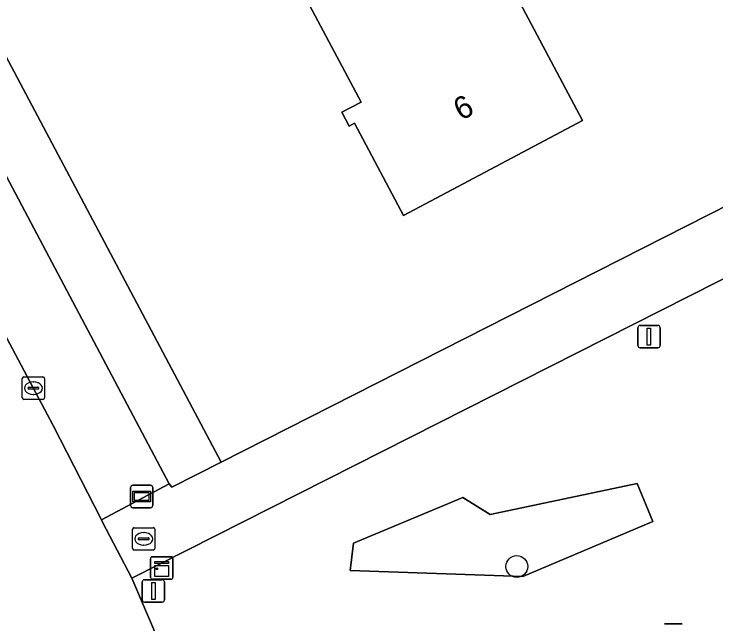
# Model space of a CAD drawing. Extents: x 162417 to 163722, y 384268 to 385417.
# Drawn here: x 163569.95 to 163601.33, y 384787.57 to 384814.82 of the extents above; entities that cross this region are included whole.
import ezdxf

# ---------------------------------------------------------------- set-up
doc = ezdxf.new("R2010")
doc.units = 0
for name, color, linetype in [('IMGEO_Berm_groen', 7, 'Continuous'), ('IMGEO_Boom', 7, 'Continuous'), ('IMGEO_Brandkraan', 7, 'Continuous'), ('IMGEO_Erf', 7, 'Continuous'), ('IMGEO_Groenvoorziening', 7, 'Continuous'), ('IMGEO_Kast', 7, 'Continuous'), ('IMGEO_Kolk', 7, 'Continuous'), ('IMGEO_Lichtmast', 7, 'Continuous'), ('IMGEO_Pand', 7, 'Continuous'), ('IMGEO_Pand_nummerreeks', 7, 'Continuous'), ('IMGEO_Rijbaan_lokaal_gesloten', 7, 'Continuous'), ('IMGEO_Verklikker', 7, 'Continuous'), ('IMGEO_Voetpad_open', 7, 'Continuous')]:
    doc.layers.add(name, color=color, linetype=linetype)

msp = doc.modelspace()

# ---------------------------------------------------------------- linework, layer by layer
at = {"layer": 'IMGEO_Berm_groen'}
msp.add_lwpolyline([(163567.994, 384810.595), (163566.174, 384809.627), (163566.069, 384809.515), (163565.334, 384808.395), (163571.704, 384796.445), (163573.858, 384792.219), (163576.893, 384793.832)], close=True, dxfattribs=at)
at = {"layer": 'IMGEO_Boom'}
msp.add_circle((163592.424, 384790.139), 0.489, dxfattribs=at)
at = {"layer": 'IMGEO_Brandkraan'}
for p, q in [((163575.25, 384790.949), (163575.25, 384791.801)), ((163575.325, 384791.875), (163576.177, 384791.875)), ((163575.738, 384791.655), (163575.763, 384791.655)), ((163576.251, 384791.801), (163576.251, 384790.949)), ((163575.509, 384791.369), (163575.509, 384791.381)), ((163575.947, 384791.332), (163575.549, 384791.332)), ((163575.552, 384791.418), (163575.95, 384791.418)), ((163575.993, 384791.381), (163575.993, 384791.369)), ((163575.761, 384791.095), (163575.736, 384791.095)), ((163576.177, 384790.875), (163575.325, 384790.875))]:
    msp.add_line(p, q, dxfattribs=at)
for points in [[(163575.25, 384790.949), (163575.25, 384791.801)], [(163575.325, 384791.875), (163576.177, 384791.875)], [(163576.251, 384791.801), (163576.251, 384790.949)], [(163576.177, 384790.875), (163575.325, 384790.875)]]:
    msp.add_lwpolyline(points, dxfattribs=at)
for centre, radius, start, end in [((163575.327, 384791.799), 0.0765, 91.552, 178.448), ((163575.327, 384791.799), 0.0765, 91.552, 178.448), ((163576.175, 384791.799), 0.0765, 1.552, 88.448), ((163576.175, 384791.799), 0.0765, 1.552, 88.448), ((163575.549, 384791.378), 0.0403, 85.8775, 175.7526), ((163575.546, 384791.368), 0.0366, 178.938, 274.7102), ((163575.95, 384791.375), 0.043, 264.8664, 352.4533), ((163575.954, 384791.38), 0.0386, 1.7309, 96.639), ((163575.327, 384790.951), 0.0765, 181.552, 268.448), ((163575.327, 384790.951), 0.0765, 181.552, 268.448), ((163576.175, 384790.951), 0.0765, 271.552, 358.448), ((163576.175, 384790.951), 0.0765, 271.552, 358.448)]:
    msp.add_arc(centre, radius, start, end, dxfattribs=at)
for centre, major_axis, ratio, start_param, end_param in [((163575.737, 384791.375), (-0.387, 0.002), 0.722429, 4.712389, 7.853982), ((163575.762, 384791.375), (-0.39, 0.002), 0.717154, 1.570796, 4.712389)]:
    msp.add_ellipse(centre, major_axis=major_axis, ratio=ratio, start_param=start_param, end_param=end_param, dxfattribs=at)
at = {"layer": 'IMGEO_Erf'}
for points in [[(163552.107, 384845.87), (163579.211, 384794.807), (163618.849, 384814.904)], [(163591.933, 384816.532), (163595.361, 384810.069), (163587.359, 384805.824), (163585.173, 384809.945), (163584.931, 384809.816), (163584.605, 384810.432), (163585.463, 384810.887), (163582.447, 384816.574)]]:
    msp.add_lwpolyline(points, dxfattribs=at)
at = {"layer": 'IMGEO_Groenvoorziening'}
msp.add_lwpolyline([(163585.393, 384778.896), (163588.913, 384780.464), (163589.864, 384780.875), (163628.147, 384799.526), (163621.295, 384812.929), (163575.222, 384789.612), (163577.885, 384783.374), (163577.57, 384783.198), (163577.982, 384782.302)], dxfattribs=at)
for points in [[(163592.689, 384789.696), (163598.502, 384792.145), (163597.802, 384793.844), (163591.241, 384792.459), (163590.02, 384793.225), (163585.127, 384791.183), (163584.983, 384789.965)], [(163592.689, 384789.696), (163584.983, 384789.965), (163585.127, 384791.183), (163590.02, 384793.225), (163591.241, 384792.459), (163597.802, 384793.844), (163598.502, 384792.145)]]:
    msp.add_lwpolyline(points, close=True, dxfattribs=at)
at = {"layer": 'IMGEO_Kast'}
for p, q in [((163576.056, 384789.648), (163576.056, 384790.489)), ((163576.056, 384790.489), (163576.056, 384789.648)), ((163576.131, 384790.573), (163576.972, 384790.573)), ((163576.972, 384790.573), (163576.131, 384790.573)), ((163577.056, 384790.498), (163577.056, 384789.657)), ((163577.056, 384789.657), (163577.056, 384790.498)), ((163576.981, 384789.573), (163576.14, 384789.573)), ((163576.14, 384789.573), (163576.981, 384789.573))]:
    msp.add_line(p, q, dxfattribs=at)
for points in [[(163576.251, 384790.363), (163576.851, 384790.363), (163576.851, 384790.278), (163576.251, 384790.278), (163576.251, 384790.363)], [(163576.251, 384790.188), (163576.851, 384790.188), (163576.851, 384789.699), (163576.251, 384789.699), (163576.251, 384790.188)]]:
    msp.add_lwpolyline(points, dxfattribs=at)
msp.add_circle((163576.335, 384790.037), 0.0377, dxfattribs=at)
for centre, start, end in [((163576.134, 384790.495), 92.4484, 184.2845), ((163576.134, 384790.495), 92.4484, 184.2845), ((163576.978, 384790.495), 2.4484, 94.2845), ((163576.978, 384790.495), 2.4484, 94.2845), ((163576.134, 384789.651), 182.4484, 274.2845), ((163576.134, 384789.651), 182.4484, 274.2845), ((163576.978, 384789.651), 272.4484, 4.2845), ((163576.978, 384789.651), 272.4484, 4.2845)]:
    msp.add_arc(centre, 0.0779, start, end, dxfattribs=at)
at = {"layer": 'IMGEO_Kolk'}
for p, q in [((163570.318, 384797.681), (163570.318, 384798.533)), ((163570.393, 384798.607), (163571.245, 384798.607)), ((163571.319, 384798.533), (163571.319, 384797.681)), ((163570.806, 384798.387), (163570.831, 384798.387)), ((163570.577, 384798.101), (163570.577, 384798.113)), ((163571.015, 384798.064), (163570.617, 384798.064)), ((163570.62, 384798.15), (163571.018, 384798.15)), ((163571.061, 384798.113), (163571.061, 384798.101)), ((163571.245, 384797.607), (163570.393, 384797.607)), ((163570.829, 384797.827), (163570.804, 384797.827))]:
    msp.add_line(p, q, dxfattribs=at)
for points in [[(163570.318, 384797.681), (163570.318, 384798.533)], [(163570.393, 384798.607), (163571.245, 384798.607)], [(163571.319, 384798.533), (163571.319, 384797.681)], [(163571.245, 384797.607), (163570.393, 384797.607)]]:
    msp.add_lwpolyline(points, dxfattribs=at)
for centre, radius, start, end in [((163570.395, 384798.531), 0.0765, 91.552, 178.448), ((163570.395, 384798.531), 0.0765, 91.552, 178.448), ((163571.243, 384798.531), 0.0765, 1.552, 88.448), ((163571.243, 384798.531), 0.0765, 1.552, 88.448), ((163570.617, 384798.11), 0.0403, 85.8775, 175.7526), ((163570.614, 384798.1), 0.0366, 178.938, 274.7102), ((163571.018, 384798.107), 0.043, 264.8664, 352.4533), ((163571.022, 384798.112), 0.0386, 1.7309, 96.639), ((163570.395, 384797.683), 0.0765, 181.552, 268.448), ((163570.395, 384797.683), 0.0765, 181.552, 268.448), ((163571.243, 384797.683), 0.0765, 271.552, 358.448), ((163571.243, 384797.683), 0.0765, 271.552, 358.448)]:
    msp.add_arc(centre, radius, start, end, dxfattribs=at)
for centre, major_axis, ratio, start_param, end_param in [((163570.805, 384798.107), (-0.387, 0.002), 0.722429, 4.712389, 7.853982), ((163570.83, 384798.107), (-0.39, 0.002), 0.717154, 1.570796, 4.712389)]:
    msp.add_ellipse(centre, major_axis=major_axis, ratio=ratio, start_param=start_param, end_param=end_param, dxfattribs=at)
at = {"layer": 'IMGEO_Lichtmast'}
for p, q in [((163597.838, 384800.01), (163597.838, 384800.81)), ((163597.838, 384800.81), (163597.838, 384800.01)), ((163597.938, 384800.91), (163598.728, 384800.91)), ((163598.728, 384800.91), (163597.938, 384800.91)), ((163598.828, 384800.81), (163598.828, 384800.01)), ((163598.828, 384800.01), (163598.828, 384800.81)), ((163598.728, 384799.91), (163597.938, 384799.91)), ((163597.938, 384799.91), (163598.728, 384799.91)), ((163575.686, 384788.648), (163575.686, 384789.448)), ((163575.686, 384789.448), (163575.686, 384788.648)), ((163575.786, 384789.548), (163576.576, 384789.548)), ((163576.576, 384789.548), (163575.786, 384789.548)), ((163576.676, 384789.448), (163576.676, 384788.648)), ((163576.676, 384788.648), (163576.676, 384789.448)), ((163576.576, 384788.548), (163575.786, 384788.548)), ((163575.786, 384788.548), (163576.576, 384788.548)), ((163599.023, 384787.574), (163599.813, 384787.574)), ((163599.813, 384787.574), (163599.023, 384787.574))]:
    msp.add_line(p, q, dxfattribs=at)
for points in [[(163598.258, 384800.785), (163598.408, 384800.785), (163598.408, 384800.035), (163598.258, 384800.035), (163598.258, 384800.785)], [(163576.106, 384789.423), (163576.256, 384789.423), (163576.256, 384788.673), (163576.106, 384788.673), (163576.106, 384789.423)]]:
    msp.add_lwpolyline(points, dxfattribs=at)
for centre, start, end in [((163597.938, 384800.81), 90, 180), ((163597.938, 384800.81), 90, 180), ((163598.728, 384800.81), 0, 90), ((163598.728, 384800.81), 360, 90), ((163597.938, 384800.01), 180, 270), ((163597.938, 384800.01), 180, 270), ((163598.728, 384800.01), 270, 0), ((163598.728, 384800.01), 270, 0), ((163575.786, 384789.448), 90, 180), ((163575.786, 384789.448), 90, 180), ((163576.576, 384789.448), 0, 90), ((163576.576, 384789.448), 360, 90), ((163575.786, 384788.648), 180, 270), ((163575.786, 384788.648), 180, 270), ((163576.576, 384788.648), 270, 0), ((163576.576, 384788.648), 270, 0)]:
    msp.add_arc(centre, 0.1, start, end, dxfattribs=at)
at = {"layer": 'IMGEO_Pand'}
msp.add_lwpolyline([(163585.226, 384826.971), (163583.797, 384826.176), (163583.892, 384825.997), (163584.307, 384825.214), (163585.85, 384822.305), (163583.685, 384821.157), (163583.495, 384821.056), (163585.013, 384818.195), (163582.34, 384816.777), (163582.447, 384816.574), (163585.463, 384810.887), (163584.605, 384810.432), (163584.931, 384809.816), (163585.173, 384809.945), (163587.359, 384805.824), (163595.361, 384810.069), (163591.933, 384816.532), (163591.144, 384818.02), (163594.128, 384819.603), (163594.478, 384819.788), (163592.982, 384822.608), (163589.427, 384829.311)], close=True, dxfattribs=at)
at = {"layer": 'IMGEO_Rijbaan_lokaal_gesloten'}
msp.add_lwpolyline([(163550.928, 384821.281), (163565.372, 384794.06), (163568.118, 384789.259), (163569.473, 384786.723), (163573.109, 384780.967), (163577.57, 384783.198), (163577.885, 384783.374), (163575.222, 384789.612), (163573.909, 384792.119), (163573.858, 384792.219), (163571.704, 384796.445), (163565.334, 384808.395), (163564.821, 384809.357), (163560.255, 384818.233)], dxfattribs=at)
at = {"layer": 'IMGEO_Verklikker'}
for p, q in [((163575.164, 384792.868), (163575.164, 384793.668)), ((163575.164, 384793.668), (163575.164, 384792.868)), ((163575.264, 384793.768), (163576.054, 384793.768)), ((163576.054, 384793.768), (163575.264, 384793.768)), ((163576.154, 384793.668), (163576.154, 384792.868)), ((163576.154, 384792.868), (163576.154, 384793.668)), ((163576.054, 384792.768), (163575.264, 384792.768)), ((163575.264, 384792.768), (163576.054, 384792.768))]:
    msp.add_line(p, q, dxfattribs=at)
for points in [[(163575.265, 384793.5), (163576.053, 384793.5), (163576.053, 384793.036), (163575.265, 384793.036), (163575.265, 384793.5)], [(163575.33, 384793.435), (163575.33, 384793.101), (163575.988, 384793.101), (163575.988, 384793.435), (163575.33, 384793.435)]]:
    msp.add_lwpolyline(points, dxfattribs=at)
for centre, start, end in [((163575.264, 384793.668), 90, 180), ((163575.264, 384793.668), 90, 180), ((163576.054, 384793.668), 0, 90), ((163576.054, 384793.668), 360, 90), ((163575.264, 384792.868), 180, 270), ((163575.264, 384792.868), 180, 270), ((163576.054, 384792.868), 270, 0), ((163576.054, 384792.868), 270, 0)]:
    msp.add_arc(centre, 0.1, start, end, dxfattribs=at)
at = {"layer": 'IMGEO_Voetpad_open'}
for points in [[(163552.107, 384845.87), (163518.056, 384909.494), (163515.928, 384908.35), (163515.734, 384908.25), (163517.932, 384903.988), (163518.096, 384903.671), (163526.026, 384888.987), (163529.708, 384881.906), (163534.572, 384872.726), (163538.645, 384865.283), (163538.754, 384865.085), (163542.031, 384858.913), (163545.302, 384852.814), (163550.786, 384842.589), (163554.272, 384836.183), (163560.032, 384825.298), (163562.999, 384819.749), (163567.994, 384810.595), (163576.893, 384793.832), (163577.006, 384793.682), (163579.211, 384794.807)], [(163621.295, 384812.929), (163628.147, 384799.526), (163630.865, 384800.823), (163624.002, 384814.334), (163645.189, 384825.054), (163646.209, 384825.591), (163644.977, 384828.162), (163641.486, 384826.348), (163641.667, 384825.959), (163626.635, 384818.288), (163626.367, 384818.629), (163618.849, 384814.904), (163579.211, 384794.807), (163577.006, 384793.682), (163576.893, 384793.832), (163573.858, 384792.219), (163573.909, 384792.119), (163575.222, 384789.612)]]:
    msp.add_lwpolyline(points, close=True, dxfattribs=at)

# ---------------------------------------------------------------- texts
at = {"layer": 'IMGEO_Pand_nummerreeks'}
msp.add_text('6', height=1, rotation=27.9432, dxfattribs=at).set_placement((163589.936, 384810.043))

doc.saveas('drawing.dxf')
